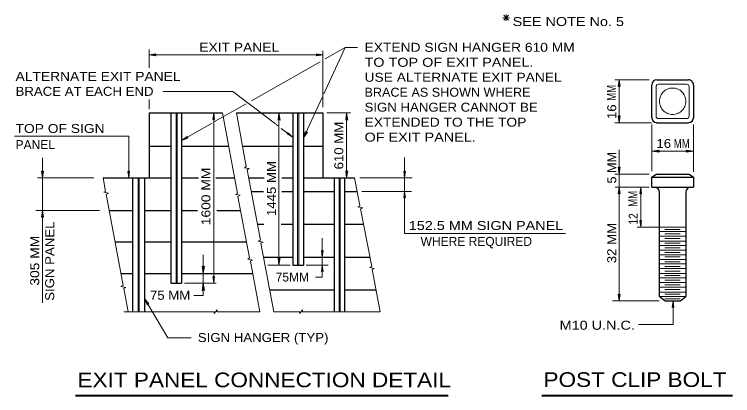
# Model space of a CAD drawing. Extents: x 312601.858 to 312602.699, y 144420.109 to 144420.704.
# Drawn here: x 312602.264 to 312602.504, y 144420.2749 to 144420.4022 of the extents above; entities that cross this region are included whole.
import ezdxf
from ezdxf.enums import TextEntityAlignment as Align

# ---------------------------------------------------------------- set-up
doc = ezdxf.new("R2010")
doc.units = 0
doc.header["$LTSCALE"] = 0.0012
doc.linetypes.add('LONG_DASHED', pattern=[7.5, 6, -1.5])
for name, color, linetype, lineweight in [('1', 7, 'Continuous', 13), ('2', 7, 'Continuous', 13), ('39', 7, 'Continuous', 13)]:
    doc.layers.add(name, color=color, linetype=linetype, lineweight=lineweight)

msp = doc.modelspace()

# ---------------------------------------------------------------- hatches: boundary and pattern name
at = {"layer": '39'}
for points in [[(312602.3524, 144420.3671), (312602.3521, 144420.3669), (312602.3524, 144420.3693), (312602.3528, 144420.3669)], [(312602.375, 144420.3671), (312602.3747, 144420.3669), (312602.375, 144420.3693), (312602.3754, 144420.3669)], [(312602.4792, 144420.3565), (312602.4794, 144420.3562), (312602.477, 144420.3565), (312602.4794, 144420.3569)], [(312602.4887, 144420.3565), (312602.4885, 144420.3569), (312602.4909, 144420.3565), (312602.4885, 144420.3562)], [(312602.375, 144420.3498), (312602.3754, 144420.35), (312602.375, 144420.3476), (312602.3747, 144420.35)], [(312602.3524, 144420.3207), (312602.3528, 144420.3209), (312602.3524, 144420.3185), (312602.3521, 144420.3209)], [(312602.3271, 144420.3179), (312602.3275, 144420.3181), (312602.3271, 144420.3157), (312602.3268, 144420.3181)], [(312602.3271, 144420.3102), (312602.3268, 144420.31), (312602.3271, 144420.3124), (312602.3275, 144420.31)]]:
    msp.add_hatch(color=256, dxfattribs=at).paths.add_polyline_path(points)

# ---------------------------------------------------------------- linework, layer by layer
at = {"layer": '1'}
for p, q in [((312602.309, 144420.3905), (312602.309, 144420.3844)), ((312602.3671, 144420.39), (312602.3671, 144420.3712)), ((312602.3674, 144420.3757), (312602.3745, 144420.3911)), ((312602.3745, 144420.3911), (312602.3679, 144420.3873)), ((312602.3745, 144420.3911), (312602.3787, 144420.3911)), ((312602.309, 144420.3887), (312602.3671, 144420.3887)), ((312602.3662, 144420.3864), (312602.3432, 144420.3733)), ((312602.4646, 144420.3803), (312602.4761, 144420.3803)), ((312602.4661, 144420.3803), (312602.4661, 144420.366)), ((312602.4784, 144420.3803), (312602.4892, 144420.3803)), ((312602.4784, 144420.3683), (312602.4784, 144420.378)), ((312602.4793, 144420.3789), (312602.4886, 144420.3789)), ((312602.4895, 144420.378), (312602.4895, 144420.3683)), ((312602.4909, 144420.3787), (312602.4909, 144420.3674)), ((312602.3137, 144420.3764), (312602.337, 144420.3764)), ((312602.3606, 144420.361), (312602.3668, 144420.3744)), ((312602.309, 144420.3738), (312602.309, 144420.3705)), ((312602.3414, 144420.3723), (312602.3309, 144420.3664)), ((312602.3306, 144420.3693), (312602.3306, 144420.3124)), ((312602.3335, 144420.3693), (312602.3386, 144420.3424)), ((312602.3382, 144420.3693), (312602.3415, 144420.3514)), ((312602.3524, 144420.3693), (312602.3524, 144420.3185)), ((312602.3684, 144420.3693), (312602.3763, 144420.3693)), ((312602.375, 144420.3693), (312602.375, 144420.3476)), ((312602.4886, 144420.3674), (312602.4793, 144420.3674)), ((312602.3301, 144420.3659), (312602.3199, 144420.3601)), ((312602.4769, 144420.366), (312602.4646, 144420.366)), ((312602.477, 144420.3499), (312602.477, 144420.3654)), ((312602.4893, 144420.366), (312602.4784, 144420.366)), ((312602.4909, 144420.3654), (312602.4909, 144420.3496)), ((312602.264, 144420.3615), (312602.3022, 144420.3615)), ((312602.3022, 144420.3615), (312602.3022, 144420.3476)), ((312602.477, 144420.3565), (312602.4909, 144420.3565)), ((312602.3944, 144420.3544), (312602.3944, 144420.3431)), ((312602.3409, 144420.351), (312602.3415, 144420.3514)), ((312602.3409, 144420.351), (312602.3424, 144420.3507)), ((312602.3418, 144420.3503), (312602.3424, 144420.3507)), ((312602.3418, 144420.3503), (312602.3462, 144420.3268)), ((312602.4646, 144420.3489), (312602.4761, 144420.3489)), ((312602.2717, 144420.3476), (312602.2905, 144420.3476)), ((312602.2937, 144420.3476), (312602.2945, 144420.3431)), ((312602.3777, 144420.3476), (312602.3794, 144420.3384)), ((312602.3794, 144420.3476), (312602.3969, 144420.3476)), ((312602.4648, 144420.3445), (312602.4761, 144420.3445)), ((312602.4733, 144420.3311), (312602.4733, 144420.3445)), ((312602.2947, 144420.3422), (312602.3003, 144420.3117)), ((312602.3379, 144420.3421), (312602.3386, 144420.3424)), ((312602.3379, 144420.3421), (312602.3394, 144420.3418)), ((312602.3387, 144420.3414), (312602.3394, 144420.3418)), ((312602.3387, 144420.3414), (312602.3426, 144420.3209)), ((312602.3801, 144420.3431), (312602.3967, 144420.3431)), ((312602.3944, 144420.3431), (312602.3944, 144420.329)), ((312602.2712, 144420.3367), (312602.2924, 144420.3367)), ((312602.2734, 144420.3367), (312602.2734, 144420.3059)), ((312602.3788, 144420.3379), (312602.3795, 144420.3383)), ((312602.3788, 144420.3379), (312602.3804, 144420.3376)), ((312602.3797, 144420.3373), (312602.3804, 144420.3376)), ((312602.3797, 144420.3373), (312602.3834, 144420.318)), ((312602.4481, 144420.329), (312602.3944, 144420.329)), ((312602.4721, 144420.3311), (312602.4884, 144420.3311)), ((312602.4884, 144420.3297), (312602.4795, 144420.3297)), ((312602.4865, 144420.3304), (312602.4814, 144420.3304)), ((312602.4865, 144420.3289), (312602.4814, 144420.3289)), ((312602.3455, 144420.3265), (312602.3462, 144420.3268)), ((312602.3455, 144420.3265), (312602.3471, 144420.3261)), ((312602.4884, 144420.3281), (312602.4795, 144420.3281)), ((312602.4884, 144420.3265), (312602.4795, 144420.3265)), ((312602.4865, 144420.3274), (312602.4814, 144420.3274)), ((312602.3464, 144420.3258), (312602.3471, 144420.3261)), ((312602.3464, 144420.3258), (312602.3507, 144420.3029)), ((312602.4884, 144420.325), (312602.4795, 144420.325)), ((312602.4865, 144420.3258), (312602.4814, 144420.3258)), ((312602.4865, 144420.3242), (312602.4814, 144420.3242)), ((312602.4884, 144420.3235), (312602.4795, 144420.3235)), ((312602.4884, 144420.3219), (312602.4795, 144420.3219)), ((312602.4865, 144420.3227), (312602.4814, 144420.3227)), ((312602.342, 144420.3205), (312602.3426, 144420.3209)), ((312602.342, 144420.3205), (312602.3435, 144420.3202)), ((312602.3429, 144420.3198), (312602.3435, 144420.3202)), ((312602.3429, 144420.3198), (312602.346, 144420.3029)), ((312602.4884, 144420.3204), (312602.4795, 144420.3204)), ((312602.4865, 144420.3212), (312602.4814, 144420.3212)), ((312602.4865, 144420.3196), (312602.4814, 144420.3196)), ((312602.3487, 144420.3185), (312602.3562, 144420.3185)), ((312602.3615, 144420.3185), (312602.3689, 144420.3185)), ((312602.3827, 144420.3177), (312602.3834, 144420.318)), ((312602.3827, 144420.3177), (312602.3842, 144420.3174)), ((312602.3836, 144420.317), (312602.3842, 144420.3174)), ((312602.3836, 144420.317), (312602.3862, 144420.3029)), ((312602.4884, 144420.3189), (312602.4795, 144420.3189)), ((312602.4884, 144420.3173), (312602.4795, 144420.3173)), ((312602.4865, 144420.318), (312602.4814, 144420.318)), ((312602.4884, 144420.3157), (312602.4795, 144420.3157)), ((312602.4865, 144420.3165), (312602.4814, 144420.3165)), ((312602.4865, 144420.315), (312602.4814, 144420.315)), ((312602.3208, 144420.3124), (312602.3314, 144420.3124)), ((312602.3271, 144420.3124), (312602.3271, 144420.3083)), ((312602.4884, 144420.3142), (312602.4795, 144420.3142)), ((312602.4884, 144420.3127), (312602.4795, 144420.3127)), ((312602.4865, 144420.3134), (312602.4814, 144420.3134)), ((312602.3006, 144420.3107), (312602.302, 144420.3029)), ((312602.4884, 144420.3111), (312602.4795, 144420.3111)), ((312602.4865, 144420.3119), (312602.4814, 144420.3119)), ((312602.4865, 144420.3103), (312602.4814, 144420.3103)), ((312602.3075, 144420.3073), (312602.3153, 144420.2942)), ((312602.4884, 144420.3095), (312602.4795, 144420.3095)), ((312602.4884, 144420.308), (312602.4795, 144420.308)), ((312602.4865, 144420.3088), (312602.4814, 144420.3088)), ((312602.4865, 144420.3072), (312602.4814, 144420.3072)), ((312602.4639, 144420.3065), (312602.4794, 144420.3065)), ((312602.3006, 144420.3029), (312602.3308, 144420.3029)), ((312602.3308, 144420.3023), (312602.3318, 144420.3036)), ((312602.3308, 144420.3023), (312602.3308, 144420.3029)), ((312602.3318, 144420.3029), (312602.3318, 144420.3036)), ((312602.3318, 144420.3029), (312602.346, 144420.3029)), ((312602.3507, 144420.3029), (312602.3594, 144420.3029)), ((312602.3594, 144420.3023), (312602.3603, 144420.3036)), ((312602.3594, 144420.3023), (312602.3594, 144420.3029)), ((312602.3603, 144420.3029), (312602.3603, 144420.3036)), ((312602.3603, 144420.3029), (312602.3862, 144420.3029)), ((312602.3153, 144420.2942), (312602.3231, 144420.2942))]:
    msp.add_line(p, q, dxfattribs=at)
at = {"layer": '1', "lineweight": 25}
for p, q in [((312602.4787, 144420.3803), (312602.4892, 144420.3803)), ((312602.477, 144420.3676), (312602.477, 144420.3786)), ((312602.4909, 144420.3786), (312602.4909, 144420.3677)), ((312602.309, 144420.3693), (312602.309, 144420.3476)), ((312602.309, 144420.3693), (312602.3335, 144420.3693)), ((312602.3163, 144420.3693), (312602.3163, 144420.3124)), ((312602.3199, 144420.3693), (312602.3199, 144420.3124)), ((312602.3382, 144420.3693), (312602.3671, 144420.3693)), ((312602.357, 144420.3693), (312602.357, 144420.3185)), ((312602.3606, 144420.3693), (312602.3606, 144420.3185)), ((312602.3671, 144420.3693), (312602.3671, 144420.3476)), ((312602.4787, 144420.366), (312602.4892, 144420.366)), ((312602.309, 144420.3582), (312602.3163, 144420.3582)), ((312602.3199, 144420.3582), (312602.3356, 144420.3582)), ((312602.3403, 144420.3582), (312602.357, 144420.3582)), ((312602.3606, 144420.3582), (312602.3671, 144420.3582)), ((312602.477, 144420.3478), (312602.4784, 144420.3489)), ((312602.4784, 144420.3489), (312602.4895, 144420.3489)), ((312602.4895, 144420.3489), (312602.4909, 144420.3478)), ((312602.2937, 144420.3476), (312602.3163, 144420.3476)), ((312602.3035, 144420.3476), (312602.3035, 144420.3029)), ((312602.3075, 144420.3476), (312602.3075, 144420.3029)), ((312602.3199, 144420.3476), (312602.3255, 144420.3476)), ((312602.3313, 144420.3476), (312602.3375, 144420.3476)), ((312602.3423, 144420.3476), (312602.3475, 144420.3476)), ((312602.3534, 144420.3476), (312602.357, 144420.3476)), ((312602.3606, 144420.3476), (312602.3777, 144420.3476)), ((312602.3709, 144420.3476), (312602.3709, 144420.3029)), ((312602.3743, 144420.3476), (312602.3743, 144420.3029)), ((312602.477, 144420.3445), (312602.477, 144420.3478)), ((312602.477, 144420.3478), (312602.4909, 144420.3478)), ((312602.4909, 144420.3478), (312602.4909, 144420.3445)), ((312602.477, 144420.3445), (312602.4909, 144420.3445)), ((312602.3431, 144420.3431), (312602.3473, 144420.3431)), ((312602.3534, 144420.3431), (312602.357, 144420.3431)), ((312602.3606, 144420.3431), (312602.3709, 144420.3431)), ((312602.3743, 144420.3431), (312602.3786, 144420.3431)), ((312602.4795, 144420.3428), (312602.4795, 144420.3081)), ((312602.4884, 144420.3428), (312602.4884, 144420.308)), ((312602.2957, 144420.3367), (312602.3035, 144420.3367)), ((312602.3075, 144420.3367), (312602.3163, 144420.3367)), ((312602.3199, 144420.3367), (312602.3252, 144420.3367)), ((312602.3317, 144420.3367), (312602.3397, 144420.3367)), ((312602.3452, 144420.3322), (312602.3474, 144420.3322)), ((312602.3531, 144420.3322), (312602.357, 144420.3322)), ((312602.3606, 144420.3322), (312602.3709, 144420.3322)), ((312602.3743, 144420.3322), (312602.3806, 144420.3322)), ((312602.2976, 144420.3263), (312602.3035, 144420.3263)), ((312602.3075, 144420.3263), (312602.3163, 144420.3263)), ((312602.3199, 144420.3263), (312602.3416, 144420.3263)), ((312602.3473, 144420.3211), (312602.357, 144420.3211)), ((312602.3606, 144420.3211), (312602.3709, 144420.3211)), ((312602.3743, 144420.3211), (312602.3828, 144420.3211)), ((312602.357, 144420.3185), (312602.3606, 144420.3185)), ((312602.2996, 144420.3157), (312602.3035, 144420.3157)), ((312602.3075, 144420.3157), (312602.3163, 144420.3157)), ((312602.3199, 144420.3157), (312602.3437, 144420.3157)), ((312602.3163, 144420.3124), (312602.3199, 144420.3124)), ((312602.3494, 144420.3102), (312602.3709, 144420.3102)), ((312602.3743, 144420.3102), (312602.3849, 144420.3102)), ((312602.4814, 144420.3065), (312602.4795, 144420.308)), ((312602.4865, 144420.3065), (312602.4884, 144420.308)), ((312602.4814, 144420.3065), (312602.4865, 144420.3065))]:
    msp.add_line(p, q, dxfattribs=at)
at = {"layer": '1'}
for points in [[(312602.3113, 144420.3884), (312602.309, 144420.3887), (312602.3113, 144420.389), (312602.311, 144420.3887)], [(312602.3649, 144420.389), (312602.3671, 144420.3887), (312602.3649, 144420.3884), (312602.3651, 144420.3887)], [(312602.4658, 144420.3781), (312602.4661, 144420.3803), (312602.4664, 144420.3781), (312602.4661, 144420.3783)], [(312602.3303, 144420.3671), (312602.3306, 144420.3693), (312602.3309, 144420.3671), (312602.3306, 144420.3673)], [(312602.4664, 144420.3683), (312602.4661, 144420.366), (312602.4658, 144420.3683), (312602.4661, 144420.368)], [(312602.3553, 144420.3628), (312602.357, 144420.3612), (312602.355, 144420.3624), (312602.3554, 144420.3624)], [(312602.3619, 144420.3629), (312602.3606, 144420.361), (312602.3613, 144420.3631), (312602.3615, 144420.3628)], [(312602.322, 144420.3609), (312602.3199, 144420.3601), (312602.3217, 144420.3614), (312602.3217, 144420.3611)], [(312602.4664, 144420.3512), (312602.4661, 144420.3489), (312602.4658, 144420.3512), (312602.4661, 144420.3509)], [(312602.2737, 144420.3499), (312602.2734, 144420.3476), (312602.2731, 144420.3499), (312602.2734, 144420.3496)], [(312602.3025, 144420.3499), (312602.3022, 144420.3476), (312602.3019, 144420.3499), (312602.3022, 144420.3496)], [(312602.3947, 144420.3499), (312602.3944, 144420.3476), (312602.3941, 144420.3499), (312602.3944, 144420.3496)], [(312602.4658, 144420.3423), (312602.4661, 144420.3445), (312602.4664, 144420.3423), (312602.4661, 144420.3425)], [(312602.473, 144420.3423), (312602.4733, 144420.3445), (312602.4736, 144420.3423), (312602.4733, 144420.3425)], [(312602.3941, 144420.3409), (312602.3944, 144420.3431), (312602.3947, 144420.3409), (312602.3944, 144420.3411)], [(312602.2731, 144420.3345), (312602.2734, 144420.3367), (312602.2737, 144420.3345), (312602.2734, 144420.3347)], [(312602.4736, 144420.3334), (312602.4733, 144420.3311), (312602.473, 144420.3334), (312602.4733, 144420.3331)], [(312602.3672, 144420.3234), (312602.3669, 144420.3211), (312602.3666, 144420.3234), (312602.3669, 144420.3231)], [(312602.3666, 144420.3163), (312602.3669, 144420.3185), (312602.3672, 144420.3163), (312602.3669, 144420.3165)], [(312602.3309, 144420.3147), (312602.3306, 144420.3124), (312602.3303, 144420.3147), (312602.3306, 144420.3144)], [(312602.3084, 144420.3052), (312602.3075, 144420.3073), (312602.3089, 144420.3055), (312602.3085, 144420.3056)], [(312602.4664, 144420.3088), (312602.4661, 144420.3065), (312602.4658, 144420.3088), (312602.4661, 144420.3085)], [(312602.4838, 144420.3043), (312602.4841, 144420.3065), (312602.4844, 144420.3043), (312602.4841, 144420.3045)]]:
    msp.add_lwpolyline(points, close=True, dxfattribs=at)
for points in [[(312602.4661, 144420.357), (312602.4661, 144420.3489), (312602.4661, 144420.3445), (312602.4661, 144420.3065)], [(312602.2734, 144420.3543), (312602.2734, 144420.3476), (312602.2734, 144420.3367)], [(312602.3669, 144420.3275), (312602.3669, 144420.3211), (312602.3669, 144420.3185), (312602.3669, 144420.3144)], [(312602.3271, 144420.3219), (312602.3271, 144420.3157), (312602.3271, 144420.3124)], [(312602.4841, 144420.3065), (312602.4841, 144420.2986), (312602.4725, 144420.2986)]]:
    msp.add_lwpolyline(points, dxfattribs=at)
at = {"layer": '1', "linetype": 'LONG_DASHED'}
msp.add_circle((312602.483955, 144420.373185), 0.00442, dxfattribs=at)
at = {"layer": '1', "lineweight": 25}
for centre, start, end in [((312602.478685, 144420.378625), 90, 180), ((312602.489225, 144420.378625), 0, 90.00156), ((312602.478685, 144420.367745), 180, 270), ((312602.489225, 144420.367745), 270, 359.99844), ((312602.477835, 144420.342845), 0, 90), ((312602.490075, 144420.342845), 90, 180)]:
    msp.add_arc(centre, 0.0017, start, end, dxfattribs=at)
at = {"layer": '1'}
for centre, start, end in [((312602.47928, 144420.37803), 90, 180), ((312602.48863, 144420.37803), 0, 90), ((312602.47928, 144420.368255), 180, 270), ((312602.48863, 144420.368255), 270, 0)]:
    msp.add_arc(centre, 0.00085, start, end, dxfattribs=at)
at = {"layer": '2'}
for p, q in [((312602.4284, 144420.4011), (312602.4272, 144420.4011)), ((312602.4284, 144420.401), (312602.4275, 144420.4019)), ((312602.4284, 144420.4012), (312602.4275, 144420.4003)), ((312602.4282, 144420.401), (312602.4291, 144420.4019)), ((312602.4282, 144420.4012), (312602.4291, 144420.4003)), ((312602.4282, 144420.4011), (312602.4294, 144420.4011)), ((312602.4283, 144420.401), (312602.4283, 144420.4022)), ((312602.4283, 144420.401), (312602.4283, 144420.4022)), ((312602.4283, 144420.4012), (312602.4283, 144420.4)), ((312602.337, 144420.3764), (312602.3512, 144420.3657)), ((312602.3515, 144420.3654), (312602.352, 144420.365)), ((312602.3532, 144420.3641), (312602.357, 144420.3612)), ((312602.3646, 144420.3144), (312602.3669, 144420.3144)), ((312602.324, 144420.3083), (312602.3271, 144420.3083))]:
    msp.add_line(p, q, dxfattribs=at)
at = {"layer": '2', "linetype": 'LONG_DASHED'}
for p, q in [((312602.3181, 144420.3124), (312602.3181, 144420.3693)), ((312602.3184, 144420.3124), (312602.3184, 144420.3693)), ((312602.3586, 144420.3184), (312602.3586, 144420.3693)), ((312602.359, 144420.3185), (312602.359, 144420.3693)), ((312602.3054, 144420.3029), (312602.3054, 144420.3476)), ((312602.3057, 144420.3029), (312602.3057, 144420.3476)), ((312602.3725, 144420.3029), (312602.3725, 144420.3476)), ((312602.3729, 144420.3029), (312602.3729, 144420.3476))]:
    msp.add_line(p, q, dxfattribs=at)
at = {"layer": '2', "lineweight": 40}
for p, q in [((312602.2844, 144420.2749), (312602.4089, 144420.2749)), ((312602.4402, 144420.2749), (312602.504, 144420.2749))]:
    msp.add_line(p, q, dxfattribs=at)
at = {"layer": '2'}
for points in [[(312602.2946, 144420.3432), (312602.2939, 144420.3428), (312602.2955, 144420.3425), (312602.2948, 144420.3422)], [(312602.3003, 144420.3117), (312602.2996, 144420.3113), (312602.3012, 144420.311), (312602.3005, 144420.3107)]]:
    msp.add_lwpolyline(points, dxfattribs=at)
at = {"layer": '39'}
for points in [[(312602.3524, 144420.3671), (312602.3521, 144420.3669), (312602.3524, 144420.3693), (312602.3528, 144420.3669)], [(312602.375, 144420.3671), (312602.3747, 144420.3669), (312602.375, 144420.3693), (312602.3754, 144420.3669)], [(312602.4792, 144420.3565), (312602.4794, 144420.3562), (312602.477, 144420.3565), (312602.4794, 144420.3569)], [(312602.4887, 144420.3565), (312602.4885, 144420.3569), (312602.4909, 144420.3565), (312602.4885, 144420.3562)], [(312602.375, 144420.3498), (312602.3754, 144420.35), (312602.375, 144420.3476), (312602.3747, 144420.35)], [(312602.3524, 144420.3207), (312602.3528, 144420.3209), (312602.3524, 144420.3185), (312602.3521, 144420.3209)], [(312602.3271, 144420.3179), (312602.3275, 144420.3181), (312602.3271, 144420.3157), (312602.3268, 144420.3181)], [(312602.3271, 144420.3102), (312602.3268, 144420.31), (312602.3271, 144420.3124), (312602.3275, 144420.31)]]:
    msp.add_lwpolyline(points, close=True, dxfattribs=at)

# ---------------------------------------------------------------- texts
at = {"layer": '2'}
for s, height, width, p in [('SEE NOTE No. 5', 0.003, 1.2, (312602.4305, 144420.3983)), ('EXIT PANEL', 0.003, 1.15, (312602.3258, 144420.3897)), ('EXTEND SIGN HANGER 610 MM', 0.003, 1.15, (312602.381, 144420.3897)), ('TO TOP OF EXIT PANEL.', 0.003, 1.2, (312602.381, 144420.3847)), ('ALTERNATE EXIT PANEL', 0.003, 1.15, (312602.2644, 144420.38)), ('USE ALTERNATE EXIT PANEL', 0.003, 1.15, (312602.381, 144420.3797)), ('BRACE AT EACH END', 0.003, 1.1, (312602.2644, 144420.375)), ('BRACE AS SHOWN WHERE', 0.003, 1.05, (312602.381, 144420.3747)), ('SIGN HANGER CANNOT BE', 0.003, 1.1, (312602.381, 144420.3697)), ('EXTENDED TO THE TOP', 0.003, 1.15, (312602.381, 144420.3647)), ('TOP OF SIGN', 0.003, 1.15, (312602.2644, 144420.3626)), ('OF EXIT PANEL.', 0.003, 1.2, (312602.381, 144420.3597)), ('M10 U.N.C.', 0.003, 1.2, (312602.4462, 144420.2969)), ('SIGN HANGER (TYP)', 0.003, 1.1, (312602.3253, 144420.2928)), ('EXIT PANEL CONNECTION DETAIL', 0.0049, 1.15, (312602.2851, 144420.2777)), ('POST CLIP BOLT', 0.0049, 1.15, (312602.4408, 144420.2778))]:
    msp.add_text(s, height=height, dxfattribs=dict(at, width=width)).set_placement(p)
for s, width, p in [('MM', 0.8, (312602.465, 144420.376)), ('16 ', 1.1, (312602.4651, 144420.3703)), ('610 MM', 1.1, (312602.3739, 144420.3584)), ('5 MM', 1.05, (312602.4651, 144420.351)), ('1445 MM', 1.1, (312602.3514, 144420.34405)), ('1600 MM', 1.15, (312602.3295, 144420.3414)), ('MM', 0.8, (312602.4722, 144420.3406)), ('12', 0.85, (312602.4723, 144420.3339)), ('SIGN PANEL', 1.1, (312602.2773, 144420.3198)), ('32 MM', 1.1, (312602.4651, 144420.32585)), ('305 MM', 1.15, (312602.2723, 144420.31995))]:
    msp.add_text(s, height=0.003, rotation=90, dxfattribs=dict(at, width=width)).set_placement(p, align=Align.CENTER)
msp.add_text('PANEL', height=0.003, dxfattribs=at).set_placement((312602.2644, 144420.3572))
for s, width, p in [('16 ', 1.1, (312602.4816, 144420.3576)), ('MM', 0.8, (312602.487, 144420.3576)), ('152.5 MM SIGN PANEL', 1.2, (312602.4216, 144420.3302)), ('75 MM', 1.1, (312602.31605, 144420.3069))]:
    msp.add_text(s, height=0.003, dxfattribs=dict(at, width=width)).set_placement(p, align=Align.CENTER)
for s, p in [('WHERE REQUIRED', (312602.41835, 144420.3249)), ('75MM', (312602.3569, 144420.313))]:
    msp.add_text(s, height=0.003, dxfattribs=at).set_placement(p, align=Align.CENTER)

doc.saveas('drawing.dxf')
